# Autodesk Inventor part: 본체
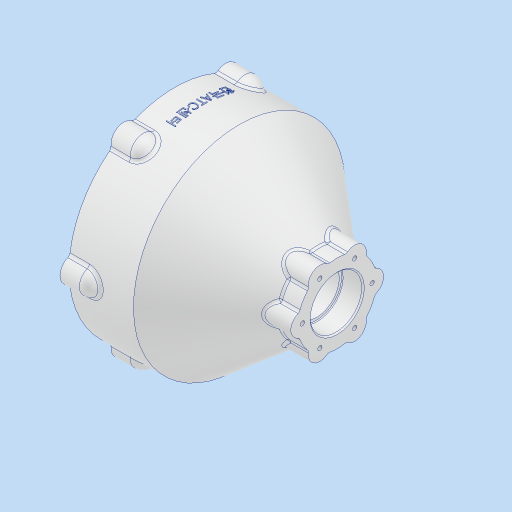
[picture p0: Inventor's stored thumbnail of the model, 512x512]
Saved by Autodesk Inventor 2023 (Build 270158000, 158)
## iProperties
Created: 2026-05
Part Number: 본체
Material: 알루미늄 6061
Document SubType Name: Modeling
Designer: home
Density: 2.7 g/cm^3
Appearance: 알루미늄 - 평지
Mass: 1980.92 g
Surface Area: 1182.24 cm^2
Volume: 733.675 cm^3
Author: home
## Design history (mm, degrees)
sketch "스케치3"
  geometry: L1 (0, 0)-(126, 0); L2 (0, 0)-(0, 82); L3 (0, 82)-(50, 82); L4 (50, 82)-(111.375, 30.5); L5 (111.375, 30.5)-(126, 30.5); L6 (126, 30.5)-(126, 0)
  constraints: 12 end point, 2 perpendicular, 1 horizontal, 1 parallel, 1 vertical
  dimensions: "d8" = 126 distance of L1.start L1.end; "d11" = 61 diameter of L5 L1; "d12" = 164 diameter of L3 L1; "d13" = 50 distance from line of L3.end L2; "d14" = 40 deg angle of L4 L3
revolve "회전2" sketch "스케치3" stored, may be unused: angle "d15" = 90 deg
sketch "스케치4"
  geometry: L1 (0, 0)-(13.5, 23.383); L2 (0, 0)-(27, 0); C1 r 30.5 at (0, 0) reference; C2 r 27 at (0, 0); C3 r 9 at (13.5, 23.383); 2 further points
  constraints: 4 end point, 2 centre point, 2 coincident, 1 equal length, 1 horizontal
  dimensions: "d16" = 54 diameter of C2; "d17" = 27 distance of L1.start L1.end; "d18" = 60 deg angle of L2 L1; "d19" = 18 diameter of C3
extrude "돌출1" join sketch "스케치4" stored distance "d20" = 10; taper "d21" = 0 deg; dims "d16" = 54, "d17" = 27, "d18" = 60 deg, "d19" = 18
sketch "스케치5"
  geometry: A1 r 9 centre (0, 0) between (8.72, 2.227) and (-8.72, 2.227) reference; 2 further points
  constraints: 1 coincident
hole "구멍1" sketch "스케치5" at (0, 0) diameter "d22" = 3.45873; stored, may be unused: countersink angle "d26" = 90 deg, drill point angle "d28" = 118 deg; dims "d23" = 8, "d24" = 7, "d25" = 2, "d27" = 10
sketch "스케치8"
  geometry: L1 (0, 0)-(39.5, 68.416); L2 (0, 0)-(79, 0); C1 r 82 at (0, 0) reference; C2 r 79 at (0, 0); C3 r 10 at (39.5, 68.416); 2 further points
  constraints: 4 end point, 2 centre point, 2 coincident, 1 equal length, 1 horizontal
  dimensions: "d38" = 158 diameter of C2; "d39" = 79 distance of L1.start L1.end; "d40" = 60 deg angle of L2 L1; "d42" = 20 diameter of C3
extrude "돌출3" join sketch "스케치8" distance "d43" = 15; taper "d44" = 0 deg
sketch "스케치9"
  geometry: L1 (0, 0)-(-39.5, 68.416); L2 (0, 0)-(79, 0); L3 (-39.5, 68.416)-(47.103, 118.416); A1 r 82 centre (0, 0) between (-32.31, 75.366) and (-49.114, 65.664) reference; A2 r 10 centre (-39.5, 68.416) between (-32.31, 75.366) and (-49.114, 65.664) reference
  constraints: 6 end point, 1 equal length, 1 horizontal
  dimensions: "d45" = 79 distance of L1.start L1.end; "d46" = 120 deg angle of L2 L1; "d49" = 100 distance of L1.end L3.end; "d50" = 90 deg angle of L1 L3
revolve "회전3" sketch "스케치9" stored, may be unused: angle "d51" = 90 deg
sketch "스케치12"
  geometry: A1 r 10 centre (0, 0) between (9.702, 2.424) and (-9.702, 2.424) reference; 2 further points
  constraints: 1 coincident
hole "구멍2" sketch "스케치12" at (0, 0) diameter "d52" = 4.917; stored, may be unused: countersink angle "d56" = 90 deg, drill point angle "d58" = 118 deg; dims "d53" = 12, "d54" = 4, "d55" = 2, "d57" = 14
sketch "스케치14"
  geometry: L1 (0, 0)-(126, 0); L2 (126, -8.72)-(126, 8.72) reference; L3 (0, 0)-(0, 73); L4 (0, 73)-(37, 73); L5 (14, 70.875)-(0, 70.875) reference; L6 (37, 73)-(37, 68); L7 (37, 68)-(42, 68); L8 (42, 68)-(42, 56); L9 (42, 56)-(62, 56); L10 (62, 56)-(62, 40); L11 (62, 40)-(78, 40); L12 (78, 40)-(78, 37); L13 (78, 37)-(82, 37); L14 (82, 37)-(82, 20); L15 (82, 20)-(94, 20); L16 (94, 20)-(94, 17.5); L17 (94, 17.5)-(110, 17.5); L18 (110, 17.5)-(110, 20); L19 (110, 20)-(126, 20); L20 (126, 20.951)-(126, 32.383) reference; L21 (126, 20)-(126, 0); 2 further points
  constraints: 36 end point, 12 perpendicular, 3 vertical, 1 horizontal, 1 midpoint, 1 parallel, 1 point on line
  dimensions: "d62" = 146 diameter of L4 L1; "d63" = 37 distance between parallel lines of L6 L3; "d64" = 40 diameter of L19 L1; "d65" = 35 diameter of L17 L1; "d66" = 16 distance between parallel lines of L18 L21; "d67" = 40 diameter of L15 L1; "d68" = 12 distance between parallel lines of L16 L14; "d69" = 136 diameter of L7 L1; "d70" = 112 diameter of L9 L1; "d71" = 80 diameter of L11 L1; "d72" = 74 diameter of L13 L1; "d73" = 16 distance between parallel lines of L12 L10; "d74" = 20 distance between parallel lines of L14 L10; "d75" = 5 distance between parallel lines of L6 L8; "d76" = 25 distance between parallel lines of L10 L6
revolve "회전4" sketch "스케치14" stored, may be unused: angle "d77" = 90 deg
chamfer "모따기1" distance "d78" = 1; stored, may be unused: second distance "d79" = 2, angle "d80" = 45 deg
fillet "모깎기1" dims "d81" = 0.6
sketch "스케치16"
  geometry: L1 (0, 0)-(31, 53.694); L2 (0, 0)-(62, 0); C1 r 56 at (0, 0) reference; C2 r 62 at (0, 0); 1 further point
  constraints: 4 end point, 2 coincident, 1 centre point, 1 equal length, 1 horizontal
  dimensions: "d87" = 124 diameter of C2; "d88" = 62 distance of L1.start L1.end; "d89" = 60 deg angle of L2 L1
hole "구멍3" sketch "스케치16" at (31, 53.694) diameter "d90" = 3.242; stored, may be unused: countersink angle "d94" = 90 deg, drill point angle "d96" = 118 deg; dims "d91" = 8, "d92" = 4, "d93" = 2, "d95" = 10
fillet "모깎기2" dims "d100" = 3
fillet "모깎기3" dims "d101" = 1
fillet "모깎기4" dims "d102" = 3
fillet "모깎기5" dims "d103" = 3
fillet "모깎기6" dims "d104" = 3
node "작업 평면4"
sketch "스케치18"
  geometry: L1 (0, 30.625)-(0, -30.625) reference; 2 further points
  constraints: 1 horizontal alignment, 1 other
  dimensions: "d106" = 20 distance from line of point (-20, 0) L1
feature "엠보싱1" sketch "스케치18" dims "d107" = 0.5, "d108" = 0
feature "ͳ耀͵耀ͷ耀͹耀ͻ耀ͽ耀Ϳ耀΁耀" dims "d8" = 126, "d11" = 61, "d12" = 164, "d13" = 50, "d14" = 40 deg, "d15" = 90 deg, "d16" = 54, "d17" = 27, "d18" = 60 deg, "d19" = 18, "d20" = 10, "d21" = 0, "d22" = 3.45873, "d23" = 8, "d24" = 7, "d25" = 2, "d26" = 90 deg, "d27" = 10, "d28" = 118 deg, "d29" = 60, "d30" = 360 deg, "d38" = 158, "d39" = 79, "d40" = 60 deg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
node "솔리드2"
pattern_circular "원형 패턴1" dims angle "d30" = 360 deg
pattern_circular "원형 패턴2" dims angle "d60" = 360 deg
pattern_circular "원형 패턴3" dims angle "d98" = 360 deg
feature "A9D066F2-1C7D-4E18-AEED-F7BC21143FA4" dims "d22" = 3.45873, "d23" = 8, "d24" = 7, "d25" = 2, "d26" = 90 deg, "d27" = 10, "d28" = 118 deg
